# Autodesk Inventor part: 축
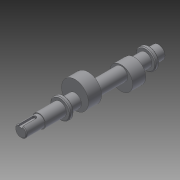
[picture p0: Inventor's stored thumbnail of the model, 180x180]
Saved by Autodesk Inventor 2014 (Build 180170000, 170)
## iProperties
Created: 2014-12
Part Number: 축
Material: 일반
Document SubType Name: Modeling
Designer: Owner
Density: 1 g/cm^3
Appearance: 기본값
Author: Owner
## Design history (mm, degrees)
sketch "스케치1"
  geometry: L1 (-90, 0)-(90, 0); L2 (-90, 0)-(-90, 7.5); L3 (-90, 7.5)-(-66, 7.5); L4 (-66, 7.5)-(-66, 8.5); L5 (-66, 8.5)-(-39, 8.5); L6 (-39, 8.5)-(-39, 13); L7 (-39, 13)-(-34, 13); L8 (-34, 13)-(-34, 8.5); L9 (72, 8.5)-(72, 13); L10 (72, 13)-(77, 13); L11 (77, 13)-(77, 8.5); L12 (77, 8.5)-(90, 8.5); L13 (90, 8.5)-(90, 0); L14 (-34, 8.5)-(72, 8.5); 2 further points
  constraints: 28 end point, 10 parallel, 3 perpendicular, 1 coincident, 1 horizontal, 1 horizontal alignment, 1 midpoint
  dimensions: "d0" = 180 distance of L1.start L1.end; "d2" = 15 diameter of L3 L1; "d3" = 17 diameter of L5 L1; "d4" = 26 diameter of L7 L1; "d5" = 24 distance of L2.end L3.end; "d6" = 27 distance of L4.end L5.end; "d7" = 5 distance of L6.end L7.end; "d8" = 13 distance of L11.end L12.end; "d9" = 5 distance of L9.end L10.end; "d10" = 17 diameter of L12 L1; "d11" = 26 diameter of L10 L1
revolve "회전1" sketch "스케치1" stored, may be unused: angle "d14" = 90 deg
node "작업 평면2"
sketch "스케치2"
  geometry: C1 r 17.5 at (0, 6); 1 further point
  constraints: 1 centre point, 1 vertical alignment
  dimensions: "d16" = 35 diameter of C1; "d17" = 6 distance of point (0, 0) C1.centre
extrude "돌출1" join sketch "스케치2" distance "d18" = 17; taper "d19" = 0 deg
node "작업 평면3"
sketch "스케치3"
  geometry: C1 r 15 at (0, -5); 1 further point
  constraints: 1 centre point, 1 vertical alignment
  dimensions: "d23" = 30 diameter of C1; "d24" = 5 distance of C1.centre point (0, 0)
extrude "돌출2" join sketch "스케치3" distance "d25" = 17; taper "d26" = 0 deg
node "작업 평면4"
sketch "스케치4"
  geometry: L1 (5.5, 0)-(-14.5, 0); L2 (5.5, 2.5)-(-14.5, 2.5); L3 (-14.5, -2.5)-(5.5, -2.5); L4 (-12, -7.5)-(-12, 7.5) reference; A1 r 2.5 centre (5.5, 0) between (5.5, -2.5) and (5.5, 2.5); A2 r 2.5 centre (-14.5, 0) between (-14.5, 2.5) and (-14.5, -2.5); 2 further points
  constraints: 8 end point, 4 point on circle, 4 tangent, 2 centre point, 1 horizontal, 1 horizontal alignment, 1 midpoint, 1 parallel
  dimensions: "d27" = 20 dimension on A1 L4; "d28" = 5 distance between parallel lines of L3 L2; "d29" = 20 distance of L3.start L3.end
chamfer "모따기1" distance "d30" = 1; stored, may be unused: second distance "d31" = 2, angle "d32" = 45 deg
extrude "돌출3" cut sketch "스케치4" distance "d33" = 3; taper "d34" = 0 deg
node "솔리드1"
other parameters: "d15" = 14.5, "d20" = 14.5
